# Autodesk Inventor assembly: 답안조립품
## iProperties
Company: 한국ATC센터
Created: 2014-07
Part Number: 답안조립품
Document SubType Name: Assembly
Designer: KYOUNG IL JANG
Mass: 6548.08 g
Surface Area: 3444.33 cm^2
Volume: 1649.71 cm^3
Density: 3.96923 g/cm^3
Author: KYOUNG IL JANG
